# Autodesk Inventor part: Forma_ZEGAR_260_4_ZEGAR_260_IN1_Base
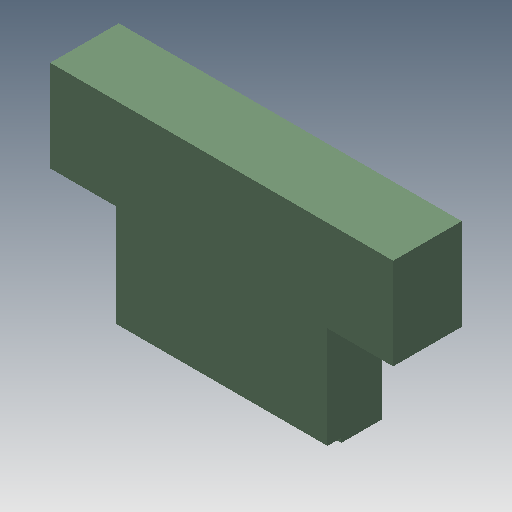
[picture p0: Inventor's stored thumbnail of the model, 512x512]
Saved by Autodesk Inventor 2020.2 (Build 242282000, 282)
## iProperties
Created: 2015-01
Part Number: Forma_ZEGAR_260_4_ZEGAR_260_IN1_Base
Material: Ogólny
Document SubType Name: Modeling
Designer: F.Stasiak
Density: 1 g/cm^3
Appearance: Domyślna
Catalog Web Link: www.expertbooks.pl
Manager: www.cadconsulting.pl
Company: Fabian Stasiak CAD Consulting
Author: F.Stasiak
Subject: Zbiór ćwiczeń. Autodesk Inventor 2020. Kurs Professional
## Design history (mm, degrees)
node "Forma_ZEGAR_260_4_ZEGAR_260_MP"
feature "Bryła5::Forma_ZEGAR_260_4_ZEGAR_260_MP"
tag "Bryła wyprowadzona1"
node "Bryła1"
feature "Forma_ZEGAR_260_4_ZEGAR_260_MP_Bodies"
